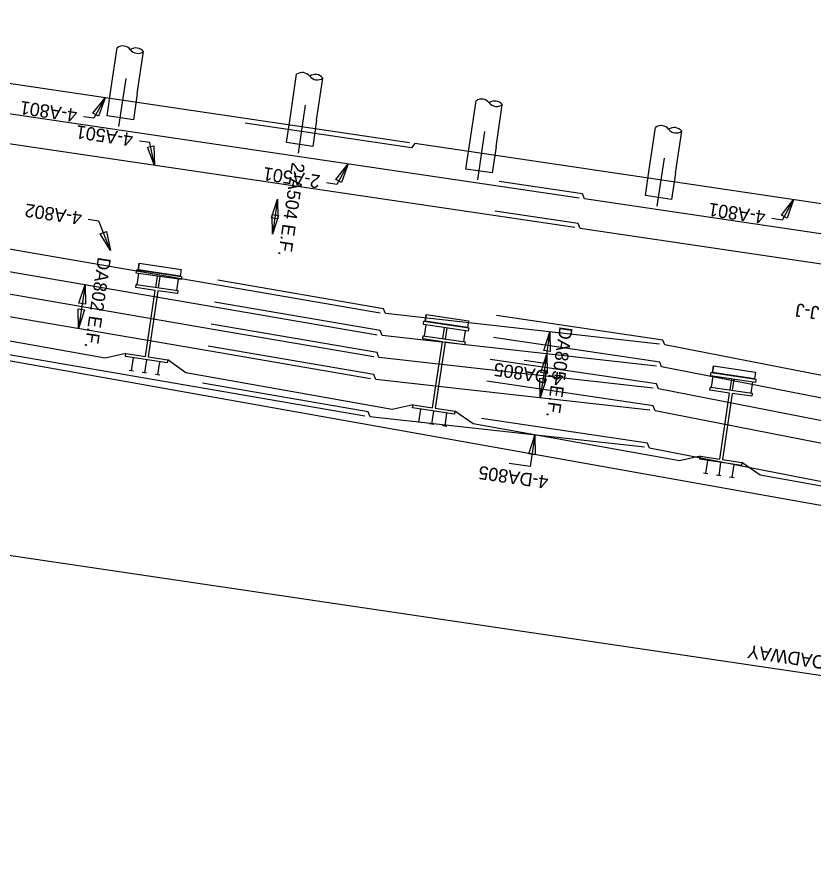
# Model space of a CAD drawing. Extents: x 1468952 to 1469933, y 573916 to 574220.
# Drawn here: x 1468989.52 to 1469019.53, y 574056.5 to 574088.79 of the extents above; entities that cross this region are included whole.
import ezdxf

# ---------------------------------------------------------------- set-up
doc = ezdxf.new("R2010")
doc.units = 0
for name, color, linetype in [('BR_P_Beam_Stl_Det', 7, 'Continuous'), ('BR_P_Gen_Phase_Construction', 7, 'Continuous'), ('BR_P_Sub_Centerline', 7, 'Continuous'), ('BR_P_Sub_Foot_Centerline', 7, 'Continuous'), ('BR_P_Sub_Text', 7, 'Continuous'), ('Default', 7, 'Continuous'), ('GE_P_CL_50', 7, 'Continuous'), ('GK_Cells', 7, 'Continuous'), ('PF_X_Ground_Line', 7, 'Continuous'), ('SV_X_Text_Elevation', 7, 'Continuous'), ('UT_X_Water', 7, 'Continuous')]:
    doc.layers.add(name, color=color, linetype=linetype)

# ---------------------------------------------------------------- blocks, each defined once
blk = doc.blocks.new('arrowOhio')
at = {"layer": 'Default'}
blk.add_lwpolyline([(0.00381, 0.000635), (0.00381, -0.000635), (0, 0)], close=True, dxfattribs=at)

msp = doc.modelspace()

# ---------------------------------------------------------------- linework, layer by layer
at = {"layer": 'BR_P_Beam_Stl_Det'}
for p, q in [((1469004.297, 574084.051), (1468972.298, 574088.788)), ((1469010.688, 574081.967), (1468972.133, 574087.675)), ((1469010.523, 574080.854), (1468971.968, 574086.562))]:
    msp.add_line(p, q, dxfattribs=at)
for points in [[(1469030.229, 574080.212), (1469004.495, 574084.021), (1469004.371, 574083.865), (1468998.106, 574084.792)], [(1469046.308, 574076.694), (1469010.886, 574081.938), (1469010.812, 574082.124), (1469007.68, 574082.588)], [(1469046.144, 574075.581), (1469010.721, 574080.825), (1469010.648, 574081.011), (1469007.515, 574081.475)]]:
    msp.add_lwpolyline(points, dxfattribs=at)
at = {"layer": 'BR_P_Gen_Phase_Construction'}
for p, q in [((1468993.051, 574086.053), (1468993.285, 574087.635)), ((1468994.04, 574085.906), (1468994.274, 574087.489)), ((1468999.81, 574085.052), (1469000.044, 574086.635)), ((1469000.799, 574084.905), (1469001.034, 574086.488)), ((1469006.57, 574084.051), (1469006.804, 574085.634)), ((1469007.559, 574083.905), (1469007.793, 574085.487)), ((1469013.329, 574083.05), (1469013.564, 574084.633)), ((1469014.319, 574082.904), (1469014.553, 574084.487))]:
    msp.add_line(p, q, dxfattribs=at)
for centre, start, end in [((1468993.494, 574087.339), 37.976, 125.1816), ((1468993.988, 574087.266), 37.976, 125.1816), ((1468994.065, 574087.785), 217.976, 305.1816), ((1469000.253, 574086.338), 37.976, 125.1816), ((1469000.748, 574086.265), 37.976, 125.1816), ((1469000.825, 574086.784), 217.976, 305.1816), ((1469007.013, 574085.338), 37.976, 125.1816), ((1469007.508, 574085.264), 37.976, 125.1816), ((1469007.584, 574085.784), 217.976, 305.1816), ((1469013.773, 574084.337), 37.976, 125.1816), ((1469014.267, 574084.264), 37.976, 125.1816), ((1469014.344, 574084.783), 217.976, 305.1816)]:
    msp.add_arc(centre, 0.362, start, end, dxfattribs=at)
at = {"layer": 'BR_P_Sub_Centerline'}
for p, q in [((1468992.904, 574085.063), (1468993.051, 574086.053)), ((1468994.04, 574085.906), (1468993.893, 574084.917)), ((1468993.893, 574084.917), (1468992.904, 574085.063)), ((1468999.664, 574084.063), (1468999.81, 574085.052)), ((1469000.799, 574084.905), (1469000.653, 574083.916)), ((1469000.653, 574083.916), (1468999.664, 574084.063)), ((1469006.423, 574083.062), (1469006.57, 574084.051)), ((1469007.559, 574083.905), (1469007.413, 574082.915)), ((1469007.413, 574082.915), (1469006.423, 574083.062)), ((1469013.183, 574082.061), (1469013.329, 574083.05)), ((1469014.319, 574082.904), (1469014.172, 574081.915)), ((1469014.172, 574081.915), (1469013.183, 574082.061))]:
    msp.add_line(p, q, dxfattribs=at)
at = {"layer": 'BR_P_Sub_Foot_Centerline'}
for p, q in [((1468994.039, 574078.706), (1468994.102, 574079.129)), ((1468994.736, 574078.603), (1468994.799, 574079.025)), ((1468994.835, 574078.588), (1468994.898, 574079.011)), ((1468995.532, 574078.485), (1468995.595, 574078.908)), ((1469004.856, 574076.771), (1469004.919, 574077.194)), ((1469005.553, 574076.668), (1469005.616, 574077.09)), ((1469005.652, 574076.653), (1469005.715, 574077.076)), ((1469006.349, 574076.55), (1469006.412, 574076.973)), ((1469015.673, 574074.836), (1469015.736, 574075.259)), ((1469016.37, 574074.733), (1469016.433, 574075.155)), ((1469016.469, 574074.718), (1469016.532, 574075.141)), ((1469017.166, 574074.615), (1469017.229, 574075.038))]:
    msp.add_line(p, q, dxfattribs=at)
at = {"layer": 'BR_P_Sub_Text'}
for p, q in [((1468980.635, 574081.53), (1468997.15, 574078.687)), ((1468980.512, 574080.703), (1468997.027, 574077.86)), ((1468980.39, 574079.875), (1468996.905, 574077.032)), ((1468980.267, 574079.048), (1468996.782, 574076.205)), ((1469003.318, 574077.799), (1468997.076, 574078.873)), ((1468997.15, 574078.687), (1469003.194, 574077.647)), ((1469003.195, 574076.971), (1468996.954, 574078.046)), ((1468997.027, 574077.86), (1469003.072, 574076.819)), ((1468980.059, 574077.644), (1468996.575, 574074.801)), ((1469003.391, 574077.613), (1469003.318, 574077.799)), ((1469013.719, 574076.46), (1469003.391, 574077.613)), ((1469013.844, 574076.617), (1469007.579, 574077.544)), ((1469003.073, 574076.144), (1468996.831, 574077.218)), ((1468996.905, 574077.032), (1469002.949, 574075.992)), ((1469003.269, 574076.785), (1469003.195, 574076.971)), ((1469013.597, 574075.633), (1469003.269, 574076.785)), ((1469013.721, 574075.789), (1469007.456, 574076.717)), ((1469013.917, 574076.431), (1469013.844, 574076.617)), ((1469002.95, 574075.316), (1468996.709, 574076.391)), ((1469035.5, 574072.215), (1469013.917, 574076.431)), ((1468996.782, 574076.205), (1469002.827, 574075.164)), ((1469003.146, 574075.958), (1469003.073, 574076.144)), ((1469013.474, 574074.805), (1469003.146, 574075.958)), ((1469013.599, 574074.962), (1469007.334, 574075.889)), ((1469013.795, 574075.603), (1469013.721, 574075.789)), ((1469035.378, 574071.387), (1469013.795, 574075.603)), ((1469003.024, 574075.13), (1469002.95, 574075.316)), ((1469002.743, 574073.913), (1468996.501, 574074.987)), ((1469013.352, 574073.978), (1469003.024, 574075.13)), ((1469013.476, 574074.134), (1469007.211, 574075.062)), ((1469013.672, 574074.776), (1469013.599, 574074.962)), ((1468996.575, 574074.801), (1469002.619, 574073.761)), ((1469035.255, 574070.56), (1469013.672, 574074.776)), ((1469013.55, 574073.948), (1469013.476, 574074.134)), ((1469002.816, 574073.727), (1469002.743, 574073.913)), ((1469013.144, 574072.574), (1469002.816, 574073.727)), ((1469035.133, 574069.732), (1469013.55, 574073.948)), ((1469013.268, 574072.731), (1469007.003, 574073.658)), ((1469013.342, 574072.545), (1469013.268, 574072.731)), ((1469034.925, 574068.328), (1469013.342, 574072.545))]:
    msp.add_line(p, q, dxfattribs=at)
at = {"layer": 'GE_P_CL_50'}
for p, q in [((1468994.111, 574079.517), (1468994.073, 574079.259)), ((1468994.005, 574079.143), (1468994.023, 574079.267)), ((1468994.023, 574079.267), (1468995.71, 574079.017)), ((1468995.699, 574079.282), (1468995.66, 574079.024)), ((1468995.692, 574078.893), (1468994.005, 574079.143)), ((1468995.71, 574079.017), (1468995.692, 574078.893)), ((1469004.928, 574077.582), (1469004.89, 574077.324)), ((1469004.822, 574077.208), (1469004.84, 574077.332)), ((1469004.84, 574077.332), (1469006.527, 574077.082)), ((1469006.516, 574077.347), (1469006.477, 574077.089)), ((1469006.509, 574076.958), (1469004.822, 574077.208)), ((1469006.527, 574077.082), (1469006.509, 574076.958)), ((1469015.745, 574075.647), (1469015.707, 574075.389)), ((1469015.639, 574075.273), (1469015.657, 574075.397)), ((1469015.657, 574075.397), (1469017.344, 574075.147)), ((1469017.333, 574075.412), (1469017.294, 574075.154)), ((1469017.326, 574075.023), (1469015.639, 574075.273)), ((1469017.344, 574075.147), (1469017.326, 574075.023))]:
    msp.add_line(p, q, dxfattribs=at)
for points in [[(1468995.699, 574079.282), (1468995.66, 574079.024), (1468994.073, 574079.259), (1468994.111, 574079.517)], [(1469006.516, 574077.347), (1469006.477, 574077.089), (1469004.89, 574077.324), (1469004.928, 574077.582)], [(1469017.333, 574075.412), (1469017.294, 574075.154), (1469015.707, 574075.389), (1469015.745, 574075.647)]]:
    msp.add_lwpolyline(points, close=True, dxfattribs=at)
at = {"layer": 'GK_Cells'}
for p, q in [((1468993.981, 574078.599), (1468993.998, 574078.712)), ((1468994.719, 574078.49), (1468993.981, 574078.599)), ((1468993.998, 574078.712), (1468995.573, 574078.479)), ((1468994.35, 574075.996), (1468994.719, 574078.49)), ((1468994.819, 574078.475), (1468994.449, 574075.981)), ((1468995.557, 574078.366), (1468994.819, 574078.475)), ((1468995.573, 574078.479), (1468995.557, 574078.366)), ((1469004.798, 574076.664), (1469004.815, 574076.777)), ((1469005.536, 574076.555), (1469004.798, 574076.664)), ((1469004.815, 574076.777), (1469006.39, 574076.544)), ((1469005.167, 574074.061), (1469005.536, 574076.555)), ((1469005.636, 574076.54), (1469005.266, 574074.046)), ((1469006.374, 574076.431), (1469005.636, 574076.54)), ((1469006.39, 574076.544), (1469006.374, 574076.431)), ((1468993.595, 574075.992), (1468993.612, 574076.105)), ((1468995.171, 574075.759), (1468993.595, 574075.992)), ((1468993.612, 574076.105), (1468994.35, 574075.996)), ((1468993.888, 574075.948), (1468993.815, 574075.454)), ((1468994.449, 574075.981), (1468995.187, 574075.872)), ((1468994.383, 574075.875), (1468994.31, 574075.381)), ((1468994.878, 574075.802), (1468994.804, 574075.307)), ((1468995.187, 574075.872), (1468995.171, 574075.759)), ((1468993.898, 574075.442), (1468993.733, 574075.466)), ((1468994.392, 574075.368), (1468994.227, 574075.393)), ((1468994.887, 574075.295), (1468994.722, 574075.32)), ((1469015.615, 574074.729), (1469015.632, 574074.842)), ((1469016.353, 574074.62), (1469015.615, 574074.729)), ((1469015.632, 574074.842), (1469017.207, 574074.609)), ((1469015.984, 574072.126), (1469016.353, 574074.62)), ((1469016.453, 574074.605), (1469016.083, 574072.111)), ((1469017.191, 574074.496), (1469016.453, 574074.605)), ((1469017.207, 574074.609), (1469017.191, 574074.496)), ((1469004.412, 574074.057), (1469004.429, 574074.17)), ((1469005.988, 574073.824), (1469004.412, 574074.057)), ((1469004.429, 574074.17), (1469005.167, 574074.061)), ((1469004.705, 574074.013), (1469004.632, 574073.519)), ((1469005.266, 574074.046), (1469006.004, 574073.937)), ((1469005.2, 574073.94), (1469005.127, 574073.446)), ((1469005.695, 574073.867), (1469005.621, 574073.372)), ((1469006.004, 574073.937), (1469005.988, 574073.824)), ((1469004.715, 574073.507), (1469004.55, 574073.531)), ((1469005.209, 574073.433), (1469005.044, 574073.458)), ((1469005.704, 574073.36), (1469005.539, 574073.385)), ((1469015.229, 574072.122), (1469015.246, 574072.235)), ((1469016.805, 574071.889), (1469015.229, 574072.122)), ((1469015.246, 574072.235), (1469015.984, 574072.126)), ((1469015.522, 574072.078), (1469015.449, 574071.584)), ((1469016.083, 574072.111), (1469016.821, 574072.002)), ((1469016.017, 574072.005), (1469015.944, 574071.511)), ((1469016.512, 574071.932), (1469016.438, 574071.437)), ((1469016.821, 574072.002), (1469016.805, 574071.889)), ((1469015.532, 574071.572), (1469015.367, 574071.596)), ((1469016.026, 574071.498), (1469015.861, 574071.523)), ((1469016.521, 574071.425), (1469016.356, 574071.45))]:
    msp.add_line(p, q, dxfattribs=at)
at = {"layer": 'PF_X_Ground_Line'}
msp.add_line((1469026.696, 574069.14), (1468981.648, 574077.187), dxfattribs=at)
for points in [[(1468993.612, 574076.105), (1468992.828, 574075.93), (1468985.216, 574077.29), (1468984.531, 574077.783)], [(1469004.429, 574074.17), (1469003.646, 574073.998), (1468995.874, 574075.386), (1468995.187, 574075.872)], [(1469015.246, 574072.235), (1469014.463, 574072.066), (1469006.691, 574073.454), (1469006.004, 574073.937)], [(1469026.065, 574070.31), (1469025.28, 574070.134), (1469017.509, 574071.522), (1469016.821, 574072.002)]]:
    msp.add_lwpolyline(points, dxfattribs=at)
at = {"layer": 'SV_X_Text_Elevation'}
for p, q in [((1468992.826, 574085.749), (1468992.407, 574084.975)), ((1468992.407, 574084.975), (1468992.011, 574085.034)), ((1468994.515, 574084.06), (1468994.12, 574084.119)), ((1468994.692, 574083.198), (1468994.515, 574084.06)), ((1469001.981, 574083.256), (1469001.562, 574082.482)), ((1469001.562, 574082.482), (1469001.166, 574082.541)), ((1468999.326, 574081.922), (1468999.132, 574080.613)), ((1469018.758, 574081.91), (1469018.339, 574081.136)), ((1468992.59, 574081.104), (1468992.194, 574081.163)), ((1468993.031, 574079.988), (1468992.59, 574081.104)), ((1469018.339, 574081.136), (1469017.943, 574081.194)), ((1468992.073, 574078.713), (1468991.828, 574077.058)), ((1469009.588, 574076.921), (1469009.413, 574075.734)), ((1469009.466, 574076.094), (1469009.221, 574074.439)), ((1469009.413, 574075.734), (1469008.621, 574075.851)), ((1469009.013, 574073.035), (1469008.837, 574071.848)), ((1469008.837, 574071.848), (1469008.046, 574071.965)), ((1469070.259, 574056.497), (1468978.025, 574070.152))]:
    msp.add_line(p, q, dxfattribs=at)
at = {"layer": 'UT_X_Water'}
for p, q in [((1468993.35, 574084.66), (1468993.618, 574086.474)), ((1469000.11, 574083.66), (1469000.378, 574085.473)), ((1469006.869, 574082.659), (1469007.138, 574084.473)), ((1469013.629, 574081.658), (1469013.897, 574083.472))]:
    msp.add_line(p, q, dxfattribs=at)

# ---------------------------------------------------------------- block references
at = {"layer": 'SV_X_Text_Elevation'}
for p, xscale, yscale, rotation in [((1468992.826, 574085.749), 191.49567999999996, 191.49568, -118.42123067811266), ((1468994.692, 574083.198), 191.49567999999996, 191.49568, 101.57876932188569), ((1469001.981, 574083.256), 191.49567999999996, 191.49568, -118.42123067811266), ((1468999.326, 574081.922), 191.49568000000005, 191.49568, -98.42123067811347), ((1469018.758, 574081.91), 191.49567999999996, 191.49568, -118.42123067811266), ((1468999.132, 574080.613), 191.49568000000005, 191.49568, 81.57876932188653), ((1468993.031, 574079.988), 191.49568000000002, 191.49568000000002, 111.57876932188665), ((1468992.073, 574078.713), 191.49568000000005, 191.49568, -98.42123067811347), ((1468991.828, 574077.058), 191.49568000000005, 191.49568, 81.57876932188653), ((1469009.588, 574076.921), 191.49568000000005, 191.49568, -98.42123067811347), ((1469009.466, 574076.094), 191.49568000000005, 191.49568, -98.42123067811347), ((1469009.221, 574074.439), 191.49568000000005, 191.49568, 81.57876932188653), ((1469009.013, 574073.035), 191.49568000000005, 191.49568, -98.42123067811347)]:
    msp.add_blockref('arrowOhio', p, dxfattribs=dict(at, xscale=xscale, yscale=yscale, rotation=rotation))

# ---------------------------------------------------------------- texts
for s, rotation, p in [('4-A801', 171.5788, (1468991.8, 574085.318)), ('4-A501', 171.5788, (1468993.909, 574084.403)), ('2-A501', 171.5788, (1469000.956, 574082.825)), ('2-A504 E.F.', 261.5788, (1468999.864, 574083.332)), ('4-A802', 171.5788, (1468991.983, 574081.447)), ('4-A801', 171.5788, (1469017.732, 574081.478)), ('DA802 E.F.', 261.5788, (1468992.558, 574079.763)), ('SEE VIEW J-J', 171.5788, (1469023.137, 574077.377)), ('DA805 E.F.', 261.5788, (1469009.951, 574077.148)), ('4-DA805', 171.5788, (1469010.126, 574075.38)), ('4-DA805', 171.5788, (1469009.55, 574071.494)), ('MEASURED PERPENDICULAR TO C ROADWAY', 171.5788, (1469031.992, 574062.924))]:
    msp.add_text(s, height=0.5, rotation=rotation, dxfattribs=at).set_placement(p)

doc.saveas('drawing.dxf')
